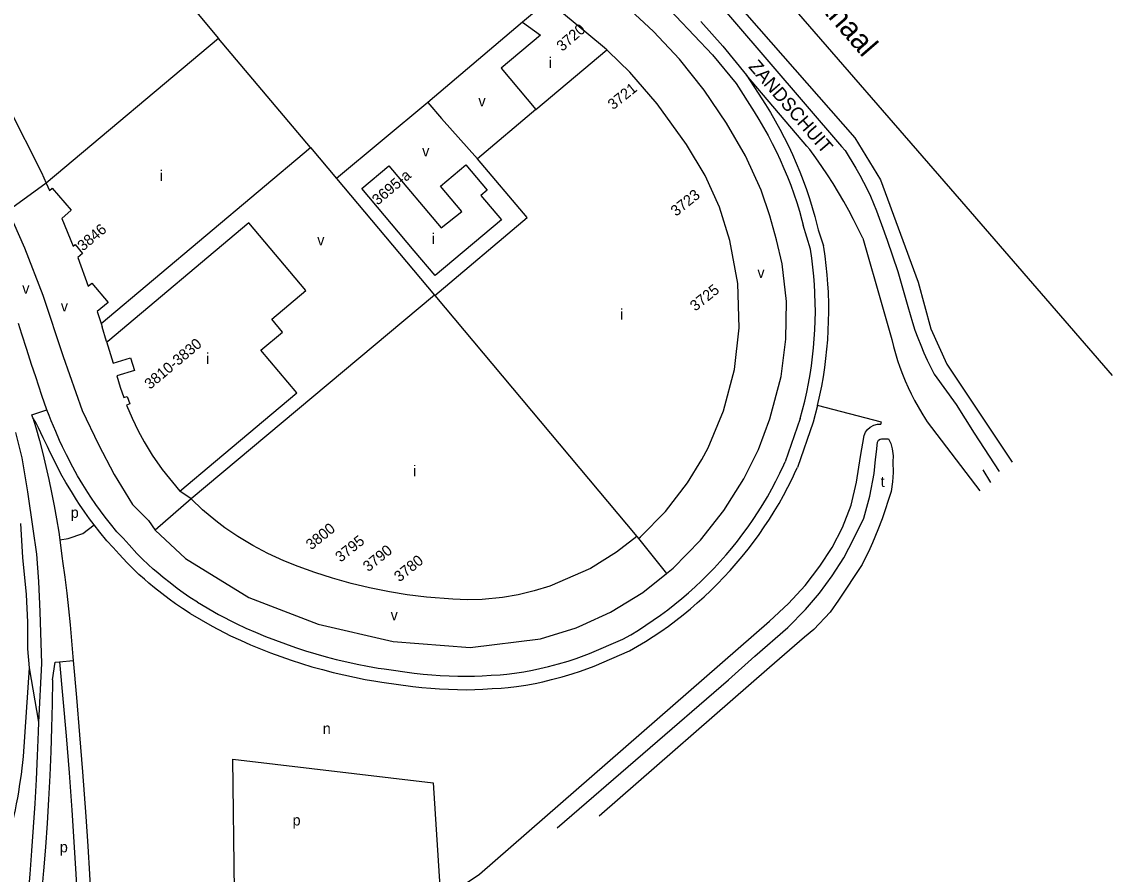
# Model space of a CAD drawing. Extents: x 154765 to 156627, y 383996 to 386132.
# Drawn here: x 156222.1 to 156627.3, y 384500 to 384816.7 of the extents above; entities that cross this region are included whole.
import ezdxf

# ---------------------------------------------------------------- set-up
doc = ezdxf.new("R2010")
doc.units = 0
for name, color, linetype in [('BLT_Basislijn', 7, 'Continuous'), ('BLT_Bebouwing', 7, 'Continuous'), ('BLT_Centroide', 7, 'Continuous'), ('BLT_Huisnummer', 7, 'Continuous'), ('BLT_Huisnummer_reeks', 7, 'Continuous'), ('BLT_Huisnummer_zonder_bebouwing', 7, 'Continuous'), ('BLT_Onderverdeling_panden', 7, 'Continuous'), ('BLT_Straatnaam', 7, 'Continuous'), ('BLT_Vlakafsluiter', 7, 'Continuous'), ('BLT_Waternaam_spoorwegen', 7, 'Continuous')]:
    doc.layers.add(name, color=color, linetype=linetype)

msp = doc.modelspace()

# ---------------------------------------------------------------- linework, layer by layer
at = {"layer": 'BLT_Basislijn'}
for p, q in [((156474.41, 384816.92), (156482.67, 384807.68)), ((156482.67, 384807.68), (156491.42, 384796.94)), ((156478.79, 384804.53), (156487.54, 384793.78)), ((156373.06, 384786.74), (156378.04, 384780.82)), ((156391.5, 384765.81), (156378.04, 384780.82)), ((156514.92, 384769.32), (156513.89, 384770.54)), ((156526.76, 384770.43), (156528.04, 384768.93)), ((156231.21, 384756.8), (156217.06, 384746.54)), ((156339.02, 384758.48), (156375.48, 384715.21)), ((156541.58, 384741.43), (156543.63, 384735.59)), ((156518.1, 384739.46), (156520.02, 384733.55)), ((156534.63, 384736.37), (156541.95, 384710.86)), ((156543.63, 384735.59), (156547.71, 384723.98)), ((156547.71, 384723.98), (156551.41, 384710.89)), ((156541.95, 384710.86), (156545.44, 384698.71)), ((156251.61, 384704.65), (156252.02, 384703.45)), ((156253.65, 384697.95), (156252.02, 384703.45)), ((156561.19, 384685.76), (156569.38, 384674.58)), ((156226.23, 384669.59), (156225.9, 384670.68)), ((156511.35, 384669.28), (156505.8, 384653.24)), ((156557.92, 384669.03), (156558.61, 384668.12)), ((156558.61, 384668.12), (156578.15, 384642.46)), ((156219.83, 384664.1), (156222.15, 384654.75)), ((156222.15, 384654.75), (156224.3, 384642.1)), ((156582.17, 384645.5), (156579.36, 384650.23)), ((156224.3, 384642.1), (156226.19, 384628.37)), ((156285.1, 384639.45), (156271.63, 384627.86)), ((156285.1, 384639.45), (156280.85, 384642.33)), ((156221.62, 384630.26), (156222.42, 384617.61)), ((156226.19, 384628.37), (156227.53, 384618.95)), ((156451.27, 384624.73), (156461.75, 384611.75)), ((156227.53, 384618.95), (156228.34, 384608.73)), ((156222.42, 384617.61), (156223.77, 384603.88)), ((156228.34, 384608.73), (156228.88, 384597.42)), ((156223.77, 384603.88), (156224.3, 384593.65)), ((156228.88, 384597.42), (156229.42, 384578.31)), ((156224.3, 384593.65), (156224.3, 384583.69)), ((156433.08, 384581.99), (156445.48, 384587.31)), ((156224.3, 384583.69), (156224.84, 384576.69)), ((156434.8, 384577.3), (156447.98, 384582.97)), ((156224.84, 384576.69), (156228.27, 384556.5)), ((156356.76, 384576.24), (156367.88, 384574.65)), ((156355.97, 384571.3), (156367.41, 384569.68))]:
    msp.add_line(p, q, dxfattribs=at)
for points in [[(156357.16, 384952.81), (156362.82, 384948.29), (156390.43, 384923.73), (156464.84, 384849.93), (156531.64, 384773.61), (156541.16, 384758.02), (156555.23, 384719.97), (156559.9, 384702.65), (156565.87, 384689.49), (156590.1, 384653.16)], [(156461.21, 384876.86), (156500.12, 384832.08), (156571.29, 384749.98), (156627.31, 384685.36)], [(156445.88, 384862.4), (156459.19, 384849.23), (156526.76, 384770.43)], [(156421.97, 384854.47), (156425.35, 384852.39), (156428.58, 384850.32), (156431.77, 384848.18), (156434.92, 384845.97), (156438.01, 384843.71), (156441.07, 384841.38), (156444.07, 384838.99), (156447.03, 384836.54), (156449.93, 384834.03), (156452.78, 384831.46), (156455.59, 384828.83), (156458.33, 384826.15), (156478.79, 384804.53)], [(156461.75, 384611.75), (156464.21, 384613.72), (156474.33, 384624.05), (156482.97, 384635.11), (156490.49, 384646.95), (156495.84, 384657.86), (156500.12, 384669.22), (156504.26, 384684.99), (156506.07, 384698.77), (156506.3, 384712.83), (156504.66, 384726.8), (156502.61, 384735.77), (156500.12, 384744.63), (156496.89, 384754.19), (156491.08, 384766.97), (156483.95, 384779.07), (156475.68, 384791.3), (156466.5, 384802.86), (156456.87, 384813.12), (156446.58, 384822.73), (156437.3, 384830.61)], [(156487.54, 384793.78), (156494.28, 384783.32), (156496.06, 384780.43), (156497.78, 384777.49), (156499.42, 384774.52), (156501, 384771.51), (156502.51, 384768.47), (156503.95, 384765.39), (156505.32, 384762.28), (156506.62, 384759.14), (156507.84, 384755.98), (156509, 384752.78), (156510.08, 384749.56), (156511.09, 384746.32), (156512.02, 384743.05), (156512.53, 384741.11)], [(156513.89, 384770.54), (156491.42, 384796.94)], [(156491.42, 384796.94), (156498.51, 384785.99), (156500.35, 384783), (156502.12, 384779.97), (156503.82, 384776.9), (156505.45, 384773.79), (156507.01, 384770.64), (156508.5, 384767.46), (156509.92, 384764.25), (156511.26, 384761), (156512.53, 384757.73), (156513.72, 384754.43), (156514.84, 384751.1), (156515.88, 384747.74), (156516.84, 384744.37), (156517.37, 384742.37)], [(156534.63, 384736.37), (156532.96, 384739.84), (156531.23, 384743.27), (156529.42, 384746.67), (156527.55, 384750.02), (156525.6, 384753.34), (156523.59, 384756.61), (156521.51, 384759.84), (156519.36, 384763.03), (156517.14, 384766.18), (156514.92, 384769.32)], [(156528.04, 384768.93), (156532.08, 384762.3), (156533.54, 384759.76), (156534.93, 384757.18), (156536.24, 384754.55), (156537.49, 384751.9), (156538.66, 384749.21), (156539.76, 384746.49), (156540.78, 384743.75), (156541.58, 384741.43)], [(156217.06, 384746.54), (156223.08, 384732.73), (156229.96, 384715.21), (156237.53, 384692.35)], [(156516.83, 384716.17), (156516.68, 384718.95), (156516.42, 384722.28), (156516.08, 384725.61), (156515.66, 384728.93), (156515.17, 384732.26), (156512.53, 384741.11)], [(156517.37, 384742.37), (156517.73, 384740.97), (156518.1, 384739.46)], [(156521.83, 384716.45), (156521.67, 384719.28), (156521.4, 384722.73), (156521.05, 384726.17), (156520.62, 384729.6), (156520.11, 384733.03), (156520.02, 384733.55)], [(156511.35, 384669.28), (156512.25, 384672.55), (156513.06, 384675.8), (156513.8, 384679.06), (156514.46, 384682.34), (156515.05, 384685.63), (156515.56, 384688.93), (156515.99, 384692.25), (156516.35, 384695.57), (156516.62, 384698.9), (156516.83, 384702.24), (156516.95, 384705.58), (156517, 384708.93), (156516.97, 384712.27), (156516.86, 384715.61), (156516.83, 384716.17)], [(156517.82, 384674.19), (156518.69, 384678.01), (156519.37, 384681.4), (156519.98, 384684.81), (156520.51, 384688.23), (156520.96, 384691.66), (156521.32, 384695.1), (156521.61, 384698.54), (156521.82, 384702), (156521.95, 384705.45), (156522, 384708.91), (156521.97, 384712.37), (156521.86, 384715.83), (156521.83, 384716.45)], [(156551.41, 384710.89), (156552.21, 384707.97), (156553.08, 384705.06), (156554.03, 384702.19), (156555.06, 384699.34), (156556.16, 384696.52), (156557.34, 384693.73), (156558.58, 384690.97), (156559.91, 384688.24), (156561.19, 384685.76)], [(156231.48, 384672.5), (156229.55, 384677.84), (156227.28, 384684.87), (156225.79, 384689.44), (156224, 384694.99), (156222.16, 384700.72), (156220.87, 384704.59)], [(156545.44, 384698.71), (156546.07, 384696.09), (156546.78, 384693.49), (156547.57, 384690.92), (156548.43, 384688.36), (156549.37, 384685.84), (156550.39, 384683.34), (156551.47, 384680.87), (156552.63, 384678.44), (156553.87, 384676.04), (156555.17, 384673.68), (156556.54, 384671.36), (156557.92, 384669.03)], [(156237.53, 384692.35), (156244.5, 384672.33), (156250.63, 384659.68), (156256.4, 384648.53), (156263.28, 384637.37), (156269.24, 384631.39)], [(156287.41, 384601.02), (156284.61, 384602.83), (156282.11, 384604.51), (156279.87, 384606.18), (156277.23, 384608.2), (156274.61, 384610.26), (156272.62, 384611.95), (156270.99, 384613.37), (156269.03, 384615.08), (156266.94, 384617.1), (156264.84, 384619.2), (156261.99, 384622.32), (156259.76, 384624.81), (156257.42, 384627.21), (156255.05, 384630.16), (156253.07, 384632.71), (156251.33, 384635.06), (156249.6, 384637.42), (156247.76, 384640.13), (156246.64, 384641.83), (156244.82, 384644.74), (156242.87, 384648.03), (156241.06, 384651.19), (156238.7, 384655.82), (156237.21, 384658.85), (156236.11, 384661.17), (156234.75, 384664.48), (156233.07, 384668.49), (156232.25, 384670.5), (156231.48, 384672.5)], [(156384.99, 384495.16), (156392.18, 384500), (156500, 384594.02), (156506.97, 384600.57), (156513.16, 384607.22), (156518.68, 384614.43), (156523.27, 384621.43), (156527.12, 384628.86), (156530.37, 384637.07), (156532.31, 384645.68), (156533.83, 384655.16), (156535.09, 384663.04), (156535.64, 384664.22), (156536.39, 384665.22), (156537.42, 384666.13), (156538.72, 384666.82), (156540.06, 384667.19), (156541.36, 384667.25), (156541.56, 384668.02), (156517.82, 384674.19)], [(156517.82, 384674.19), (156516.17, 384667.96), (156510.36, 384651.17)], [(156569.38, 384674.58), (156575.97, 384663.82), (156585.33, 384649.64)], [(156226.23, 384669.59), (156227.32, 384665.92), (156228.65, 384661.13), (156229.91, 384656.32), (156231.1, 384651.5), (156232.2, 384646.65), (156233.22, 384641.79), (156234.17, 384636.91), (156235.04, 384632.02), (156235.83, 384627.11), (156236.24, 384624.25)], [(156248.98, 384629.83), (156247.31, 384632.09), (156245.52, 384634.54), (156243.61, 384637.35), (156242.43, 384639.13), (156240.55, 384642.14), (156238.55, 384645.51), (156236.67, 384648.81), (156234.23, 384653.58), (156232.71, 384656.68), (156231.62, 384658.97), (156230.03, 384662.12), (156228.32, 384665.88), (156227.28, 384667.78), (156226.23, 384669.59)], [(156421.08, 384517.18), (156484.73, 384572.16), (156494.56, 384581.02), (156506.76, 384591.71), (156513.32, 384598.34), (156518.51, 384604.44), (156523.26, 384610.87), (156527.62, 384617.58), (156531.34, 384624.67), (156535.04, 384632.33), (156537.31, 384640.52), (156538.82, 384648.89), (156539.4, 384654.07), (156539.72, 384656.88), (156540.14, 384660.47), (156540.43, 384661.22), (156541.08, 384661.7), (156541.56, 384661.76), (156544.19, 384661.76), (156545.11, 384660.02), (156545.6, 384658.04), (156545.89, 384655.45), (156545.84, 384653.22), (156545.86, 384649.21), (156545.64, 384645.76), (156545.17, 384642.17), (156541.86, 384632.1), (156540.24, 384627.96), (156538.21, 384623.12), (156537.2, 384620.87), (156534.42, 384615.06), (156525.65, 384601.78), (156522.51, 384597.39), (156516.38, 384590.88), (156512.96, 384588.07), (156500, 384576.77), (156436.72, 384521.59)], [(156445.48, 384587.31), (156448.41, 384588.99), (156451.24, 384590.71), (156454.03, 384592.5), (156456.78, 384594.35), (156459.49, 384596.26), (156462.15, 384598.24), (156464.77, 384600.28), (156467.33, 384602.38), (156469.85, 384604.53), (156472.32, 384606.75), (156474.73, 384609.02), (156477.09, 384611.35), (156479.4, 384613.74), (156481.65, 384616.17), (156483.84, 384618.66), (156485.97, 384621.2), (156488.04, 384623.79), (156490.05, 384626.42), (156492.01, 384629.1), (156493.89, 384631.83), (156495.72, 384634.6), (156497.47, 384637.41), (156499.17, 384640.26), (156500.79, 384643.15), (156502.35, 384646.08), (156503.84, 384649.04), (156505.27, 384652.05), (156505.8, 384653.24)], [(156447.98, 384582.97), (156450.95, 384584.68), (156453.89, 384586.47), (156456.78, 384588.32), (156459.62, 384590.23), (156462.43, 384592.21), (156465.18, 384594.26), (156467.89, 384596.37), (156470.55, 384598.54), (156473.15, 384600.78), (156475.7, 384603.07), (156478.2, 384605.43), (156480.64, 384607.84), (156483.03, 384610.3), (156485.36, 384612.82), (156487.63, 384615.4), (156489.84, 384618.03), (156491.98, 384620.71), (156494.06, 384623.43), (156496.08, 384626.21), (156498.04, 384629.03), (156499.92, 384631.9), (156501.74, 384634.81), (156503.5, 384637.76), (156505.18, 384640.75), (156506.79, 384643.78), (156508.33, 384646.85), (156509.8, 384649.95), (156510.36, 384651.17)], [(156269.24, 384631.39), (156271.63, 384627.86)], [(156236.24, 384624.25), (156239.4, 384624.71), (156244.83, 384626.62), (156248.98, 384629.83)], [(156284.7, 384596.82), (156281.86, 384598.66), (156279.23, 384600.43), (156276.86, 384602.19), (156274.17, 384604.25), (156271.45, 384606.39), (156269.35, 384608.16), (156267.71, 384609.6), (156265.65, 384611.4), (156263.43, 384613.54), (156261.22, 384615.75), (156258.28, 384618.96), (156256.11, 384621.4), (156253.68, 384623.89), (156251.12, 384627.06), (156248.98, 384629.83)], [(156271.63, 384627.86), (156282.97, 384617.27), (156306.5, 384602.76), (156332.3, 384592.86), (156360.18, 384586.4), (156388.72, 384584.18), (156414.89, 384587.39), (156428.16, 384591.52), (156430.55, 384592.61)], [(156236.24, 384624.25), (156236.54, 384622.19), (156237.17, 384617.26), (156237.28, 384616.29)], [(156237.28, 384616.29), (156238.12, 384610.38), (156238.87, 384604.46), (156239.54, 384598.54), (156240.13, 384592.6), (156240.65, 384586.65), (156241.08, 384580.7), (156241.16, 384579.4)], [(156430.55, 384592.61), (156440.94, 384597.34), (156452.9, 384604.69), (156461.75, 384611.75)], [(156287.41, 384601.02), (156295.27, 384596.54), (156301.75, 384593.13)], [(156284.7, 384596.82), (156292.86, 384592.16), (156299.66, 384588.59)], [(156301.75, 384593.13), (156305.39, 384591.45), (156309.01, 384589.87), (156312.67, 384588.35), (156316.36, 384586.91), (156320.07, 384585.54), (156323.81, 384584.25), (156327.58, 384583.03), (156331.36, 384581.89), (156335.17, 384580.81), (156339, 384579.82), (156342.85, 384578.9), (156346.72, 384578.06), (156350.6, 384577.29), (156354.51, 384576.6), (156356.76, 384576.24)], [(156299.66, 384588.59), (156303.34, 384586.89), (156307.06, 384585.26), (156310.8, 384583.71), (156314.58, 384582.24), (156318.39, 384580.84), (156322.22, 384579.51), (156326.08, 384578.26), (156329.96, 384577.09), (156333.87, 384575.99), (156337.8, 384574.97), (156341.74, 384574.03), (156345.7, 384573.16), (156349.68, 384572.38), (156353.68, 384571.67), (156355.97, 384571.3)], [(156233.59, 384572.18), (156234.53, 384578.78), (156236.19, 384578.93)], [(156236.19, 384578.93), (156237.43, 384565.16), (156238.6, 384551.38), (156239.69, 384537.6), (156240.7, 384523.81), (156241.63, 384510.01), (156242.26, 384500)], [(156241.16, 384579.4), (156242.41, 384565.61), (156243.58, 384551.82), (156244.67, 384538.02), (156245.89, 384521.36)], [(156367.88, 384574.65), (156371.23, 384574.34), (156374.46, 384574.07), (156377.61, 384573.87), (156380.88, 384573.71), (156384.13, 384573.58), (156387.21, 384573.54), (156390.39, 384573.57), (156393.15, 384573.69), (156396.6, 384573.92), (156399.92, 384574.1), (156402.33, 384574.32), (156405.27, 384574.67), (156408.66, 384575.15), (156411.94, 384575.77), (156414.6, 384576.36), (156417.79, 384577.13), (156421.58, 384578.13), (156425.1, 384579.18), (156428.14, 384580.18), (156433.08, 384581.99)], [(156224.84, 384576.69), (156222.6, 384543.73), (156222.39, 384541.55), (156222.13, 384539.38), (156221.83, 384536.99), (156221.55, 384534.88), (156221.2, 384532.61), (156220.9, 384530.49), (156220.5, 384528.38), (156220.08, 384526.14), (156219.64, 384523.94), (156219.16, 384521.76), (156218.63, 384519.59), (156218.2, 384517.5), (156217.67, 384515.17), (156216.75, 384510.87), (156216.23, 384508.74), (156215.68, 384506.44), (156215.19, 384504.21), (156214.7, 384502.11), (156213.86, 384498.76)], [(156367.41, 384569.68), (156370.79, 384569.36), (156374.09, 384569.08), (156377.32, 384568.88), (156380.66, 384568.71), (156383.99, 384568.58), (156387.2, 384568.54), (156390.52, 384568.57), (156393.42, 384568.69), (156396.91, 384568.93), (156400.28, 384569.11), (156402.85, 384569.35), (156405.92, 384569.71), (156409.47, 384570.22), (156412.94, 384570.87), (156415.73, 384571.49), (156419.01, 384572.29), (156422.93, 384573.32), (156426.59, 384574.41), (156429.79, 384575.46), (156434.8, 384577.3)], [(156233.59, 384572.18), (156233.44, 384563.29), (156233.22, 384554.41), (156232.92, 384545.53), (156232.53, 384536.65), (156232.07, 384527.78), (156231.52, 384518.91), (156230.9, 384510.05), (156230.2, 384501.19), (156230.09, 384500)], [(156228.27, 384556.5), (156228.17, 384552.86), (156227.85, 384544)], [(156227.85, 384544), (156227.45, 384535.15), (156226.97, 384526.3), (156226.41, 384517.45), (156225.77, 384508.61), (156225.08, 384500)], [(156301.14, 384493.68), (156300.55, 384542.72), (156375.01, 384533.94), (156377.47, 384495.36)], [(156245.89, 384521.36), (156246.62, 384510.41), (156247.26, 384500)], [(156225.08, 384499.98), (156224.31, 384491.47)], [(156225.08, 384500), (156225.08, 384499.98)], [(156230.09, 384499.98), (156229.3, 384491.13), (156229.05, 384488.58)], [(156230.09, 384500), (156230.09, 384499.98)], [(156242.26, 384500), (156242.26, 384499.98)], [(156242.26, 384499.98), (156243.2, 384483.29)], [(156247.26, 384500), (156247.27, 384499.98)], [(156247.27, 384499.98), (156248.31, 384481.14)]]:
    msp.add_lwpolyline(points, dxfattribs=at)
at = {"layer": 'BLT_Bebouwing'}
for p, q in [((156408.15, 384816.57), (156373.06, 384786.74)), ((156413.14, 384784.18), (156391.5, 384765.81)), ((156329.35, 384769.98), (156339.02, 384758.48)), ((156327.64, 384716.87), (156306.5, 384742.05)), ((156375.48, 384715.21), (156285.1, 384639.45)), ((156324.36, 384678.9), (156310.98, 384694.72)), ((156450.63, 384625.49), (156451.27, 384624.73))]:
    msp.add_line(p, q, dxfattribs=at)
for points in [[(156184.26, 384838.5), (156201.43, 384812.17), (156208.56, 384800.4), (156215.34, 384788.41), (156217.22, 384784.97), (156229.41, 384760.71), (156231.21, 384756.8)], [(156439.52, 384806.36), (156438.71, 384807.08), (156422.69, 384820.28), (156417.18, 384824.17)], [(156408.15, 384816.57), (156414.81, 384811.8), (156400.22, 384799.51), (156413.14, 384784.18)], [(156451.27, 384624.73), (156451.98, 384625.35), (156461.28, 384634.8), (156469.5, 384645.4), (156474.8, 384654.05), (156477.14, 384658.47), (156482.87, 384672.14), (156486.9, 384687.52), (156488.65, 384703.03), (156488.14, 384719.51), (156485.26, 384735.52), (156481.33, 384747.82), (156476, 384759.57), (156469.1, 384771.18), (156458.19, 384786.26), (156448.02, 384797.98), (156440.06, 384805.89), (156439.54, 384806.38), (156439.52, 384806.36)], [(156373.06, 384786.74), (156339.02, 384758.48)], [(156251.61, 384704.65), (156329.35, 384769.98)], [(156375.62, 384715.04), (156409.9, 384743.97), (156391.5, 384765.81)], [(156231.21, 384756.8), (156232.41, 384754.08), (156233.43, 384754.87), (156240.47, 384746.71), (156236.97, 384743.7), (156241.21, 384733.41), (156241.95, 384733.97), (156244.74, 384730.68), (156242.89, 384729.12), (156246.84, 384718.55), (156248.11, 384719.61), (156254.18, 384712.4), (156250.11, 384709.05), (156251.61, 384704.65)], [(156306.5, 384742.05), (156254.1, 384698), (156253.65, 384697.95)], [(156310.98, 384694.72), (156319.01, 384701.42), (156315.05, 384706.27), (156327.64, 384716.87)], [(156375.48, 384715.21), (156375.62, 384715.04), (156375.62, 384715.04)], [(156253.65, 384697.95), (156256.04, 384689.92), (156262.56, 384691.87), (156263.98, 384687.11), (156257.47, 384685.12), (156258.71, 384680.99), (156260.02, 384677.12), (156261.28, 384677.54), (156262.31, 384674.77), (156261.09, 384674.25), (156263.11, 384669.48), (156265.33, 384664.8), (156267.59, 384660.64), (156270.59, 384655.72), (156274.28, 384650.36), (156280.85, 384642.33)], [(156280.85, 384642.33), (156294.1, 384653.47), (156324.36, 384678.9)], [(156450.63, 384625.49), (156443.16, 384619.63), (156433.46, 384613.54), (156418.37, 384606.98), (156412.5, 384605.23), (156406.53, 384603.8), (156400.74, 384602.8), (156393.19, 384602.08), (156387.72, 384601.92), (156382.24, 384602.15), (156372.45, 384602.96), (156365.29, 384603.82), (156358.72, 384604.93), (156351.31, 384606.42), (156344.57, 384608.03), (156337.6, 384610.01), (156331, 384612.09), (156324.79, 384614.28), (156319.52, 384616.38), (156313.49, 384619.15), (156307.94, 384622.14), (156302.44, 384625.43), (156297.51, 384628.74), (156294.21, 384631.3), (156289.32, 384635.41), (156285.1, 384639.45)]]:
    msp.add_lwpolyline(points, dxfattribs=at)
msp.add_lwpolyline([(156348.51, 384754.76), (156358.56, 384763.22), (156377.98, 384740.13), (156385.64, 384746.31), (156377.76, 384755.68), (156387.13, 384763.57), (156395.02, 384754.19), (156392.7, 384752.24), (156400.35, 384743.14), (156375.71, 384722.41), (156367.92, 384731.67)], close=True, dxfattribs=at)
at = {"layer": 'BLT_Onderverdeling_panden'}
for p, q in [((156329.35, 384769.98), (156295.22, 384810.59)), ((156375.62, 384715.04), (156450.63, 384625.49))]:
    msp.add_line(p, q, dxfattribs=at)
for points in [[(156280.84, 384827.93), (156295.22, 384810.59)], [(156417.18, 384824.17), (156408.15, 384816.57)], [(156295.22, 384810.59), (156231.21, 384756.8)], [(156413.14, 384784.18), (156439.52, 384806.36)]]:
    msp.add_lwpolyline(points, dxfattribs=at)
at = {"layer": 'BLT_Vlakafsluiter'}
for p, q in [((156225.9, 384670.68), (156231.48, 384672.5)), ((156229.42, 384578.31), (156228.27, 384556.5)), ((156236.19, 384578.93), (156241.16, 384579.4))]:
    msp.add_line(p, q, dxfattribs=at)

# ---------------------------------------------------------------- texts
at = {"layer": 'BLT_Centroide'}
for s, p in [('i', (156417.94, 384799.57)), ('v', (156391.8, 384785.3)), ('v', (156370.9, 384766.74)), ('i', (156273.41, 384757.62)), ('v', (156331.91, 384733.66)), ('i', (156374.42, 384734.14)), ('v', (156495.47, 384721.59)), ('v', (156222.3, 384715.7)), ('v', (156236.62, 384709.1)), ('i', (156444.42, 384706.09)), ('i', (156290.64, 384689.64)), ('i', (156367.53, 384647.89)), ('p', (156240.31, 384632.41)), ('v', (156359.18, 384594.38)), ('n', (156333.96, 384552.14)), ('p', (156322.74, 384518.08)), ('p', (156236.25, 384508.1))]:
    msp.add_text(s, height=4, dxfattribs=at).set_placement(p)
msp.add_text('t', height=4, rotation=1, dxfattribs=at).set_placement((156541.31, 384643.84))
at = {"layer": 'BLT_Huisnummer'}
for s, rotation, p in [('3720', 41.143, (156422.96, 384805.54)), ('3846', 40.039, (156244.87, 384731.34))]:
    msp.add_text(s, height=4, rotation=rotation, dxfattribs=at).set_placement(p)
at = {"layer": 'BLT_Huisnummer_reeks'}
for s, rotation, p in [('3695-a', 40.0735, (156354.37, 384748.39)), ('3810-3830', 40.0576, (156269.78, 384679.96)), ('3800', 38.8534, (156329.69, 384620.27)), ('3795', 38.8534, (156340.59, 384615.71)), ('3790', 38.8534, (156350.89, 384612.15)), ('3780', 38.8534, (156362.45, 384608.38))]:
    msp.add_text(s, height=4, rotation=rotation, dxfattribs=at).set_placement(p)
at = {"layer": 'BLT_Huisnummer_zonder_bebouwing'}
for s, p in [('3721', (156441.87, 384783.85)), ('3723', (156465.26, 384744.27)), ('3725', (156472.42, 384709))]:
    msp.add_text(s, height=4, rotation=38.8534, dxfattribs=at).set_placement(p)
at = {"layer": 'BLT_Straatnaam'}
msp.add_text('ZANDSCHUIT', height=5, rotation=310.8725, dxfattribs=at).set_placement((156491.91, 384799.93))
at = {"layer": 'BLT_Waternaam_spoorwegen'}
msp.add_text('Beatrixkanaal', height=7.9999, rotation=310.9054, dxfattribs=at).set_placement((156492.33, 384852.15))

doc.saveas('drawing.dxf')
